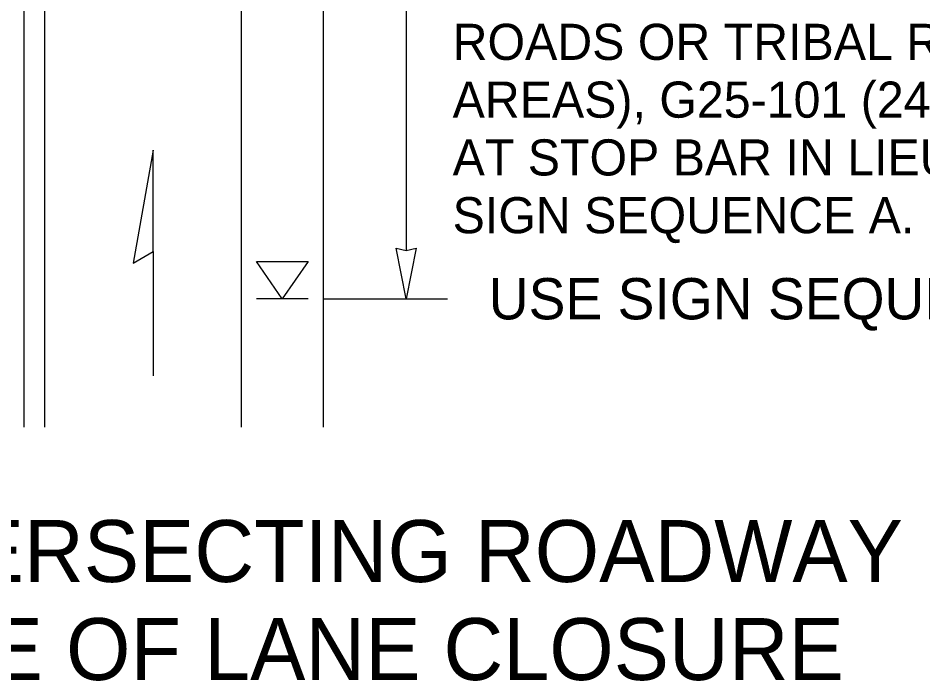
# Model space of a CAD drawing. Extents: x 99999.1 to 100095.7, y 99995 to 100010.7.
# Drawn here: x 100062.093 to 100063.846, y 100001.684 to 100002.969 of the extents above; entities that cross this region are included whole.
import ezdxf

# ---------------------------------------------------------------- set-up
doc = ezdxf.new("R2010")
doc.units = 0
for name, color, linetype in [('RD_ED_ShoulderPavedEdge', 7, 'Continuous'), ('RD_MK_LineDblYellowCenter', 7, 'Continuous'), ('RD_MK_LineEdgeWhite', 7, 'Continuous'), ('SH_DE_DetailHeading2Text', 7, 'Continuous'), ('TR_WZ_PortableSignMountBlk-Org', 7, 'Continuous'), ('TR_WZ_WorkZoneDetails', 7, 'Continuous'), ('TR_WZ_WorkZoneTextCurrent', 7, 'Continuous')]:
    doc.layers.add(name, color=color, linetype=linetype)

msp = doc.modelspace()

# ---------------------------------------------------------------- linework, layer by layer
at = {"layer": 'RD_ED_ShoulderPavedEdge'}
msp.add_lwpolyline([(100062.685, 100002.1759), (100062.685, 100003.5249)], dxfattribs=at)
at = {"layer": 'RD_MK_LineDblYellowCenter'}
for p, q in [((100062.105, 100002.1759), (100062.105, 100003.7249)), ((100062.145, 100002.1759), (100062.145, 100003.7249))]:
    msp.add_line(p, q, dxfattribs=at)
at = {"layer": 'RD_MK_LineEdgeWhite'}
msp.add_line((100062.525, 100003.5249), (100062.525, 100002.1759), dxfattribs=at)
at = {"layer": 'TR_WZ_PortableSignMountBlk-Org'}
msp.add_line((100062.655, 100002.4249), (100062.555, 100002.4249), dxfattribs=at)
msp.add_lwpolyline([(100062.605, 100002.4249), (100062.555, 100002.4968), (100062.655, 100002.4968)], close=True, dxfattribs=at)
at = {"layer": 'TR_WZ_WorkZoneDetails'}
for p, q in [((100062.845, 100003.6312), (100062.845, 100002.5187)), ((100062.3545, 100002.5164), (100062.3545, 100002.2753)), ((100062.685, 100002.4249), (100062.925, 100002.4249))]:
    msp.add_line(p, q, dxfattribs=at)
for points in [[(100062.3545, 100002.7129), (100062.316, 100002.4941), (100062.3545, 100002.5164)], [(100062.845, 100002.4249), (100062.8257, 100002.5232), (100062.845, 100002.5187), (100062.8643, 100002.5232)]]:
    msp.add_lwpolyline(points, close=True, dxfattribs=at)

# ---------------------------------------------------------------- texts
at = {"layer": 'SH_DE_DetailHeading2Text'}
for s, p in [('UNSIGNALIZED INTERSECTING ROADWAY DETAIL', (100060.5086, 100001.8759)), ('OPPOSITE OF LANE CLOSURE', (100061.3211, 100001.6859))]:
    msp.add_text(s, height=0.12, rotation=360, dxfattribs=at).set_placement(p)
at = {"layer": 'TR_WZ_WorkZoneDetails'}
for s, p in [('ROADS OR TRIBAL ROADS IN RURAL ', (100062.935, 100002.8878)), ('AREAS), G25-101 (24"x18", B/W) MAY BE USED ', (100062.935, 100002.7758)), ('AT STOP BAR IN LIEU OF FLAGGER AND ', (100062.935, 100002.6638)), ('SIGN SEQUENCE A.', (100062.935, 100002.5518))]:
    msp.add_text(s, height=0.07, dxfattribs=at).set_placement(p)
at = {"layer": 'TR_WZ_WorkZoneTextCurrent'}
msp.add_text('USE SIGN SEQUENCE A', height=0.08, dxfattribs=at).set_placement((100063.005, 100002.3849))

doc.saveas('drawing.dxf')
